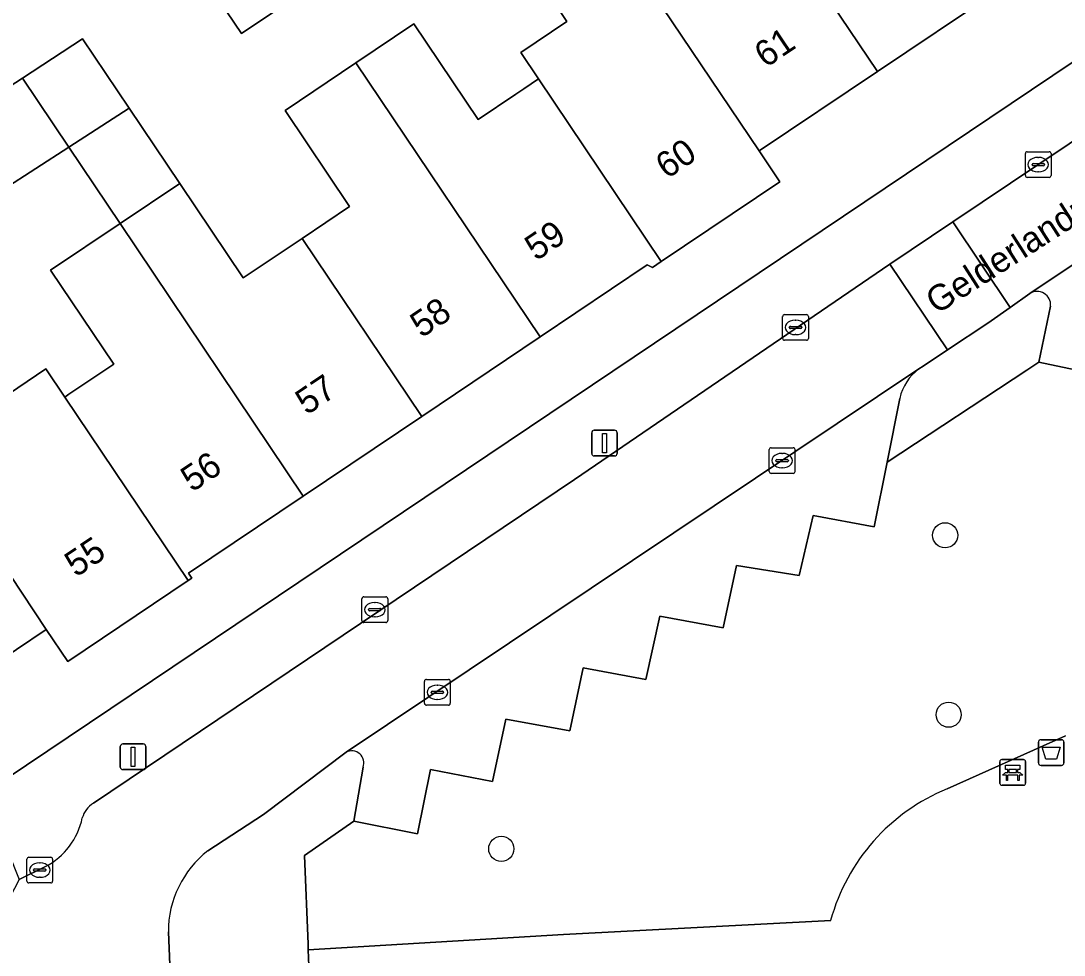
# Model space of a CAD drawing. Extents: x 158352 to 159489, y 383828 to 384603.
# Drawn here: x 158904.38 to 158944.92, y 384131.29 to 384167.59 of the extents above; entities that cross this region are included whole.
import ezdxf

# ---------------------------------------------------------------- set-up
doc = ezdxf.new("R2010")
doc.units = 0
for name, color, linetype in [('IMGEO_Afvalbak', 7, 'Continuous'), ('IMGEO_Bank', 7, 'Continuous'), ('IMGEO_Boom', 7, 'Continuous'), ('IMGEO_Erf', 7, 'Continuous'), ('IMGEO_Groenvoorziening', 7, 'Continuous'), ('IMGEO_Kolk', 7, 'Continuous'), ('IMGEO_Lichtmast', 7, 'Continuous'), ('IMGEO_Openbare_ruimte_label', 7, 'Continuous'), ('IMGEO_Pand', 7, 'Continuous'), ('IMGEO_Pand_nummerreeks', 7, 'Continuous'), ('IMGEO_Parkeervlak_open', 7, 'Continuous'), ('IMGEO_Rijbaan_lokaal_open', 7, 'Continuous'), ('IMGEO_Voetpad_halfverhard', 7, 'Continuous'), ('IMGEO_Voetpad_open', 7, 'Continuous')]:
    doc.layers.add(name, color=color, linetype=linetype)

msp = doc.modelspace()

# ---------------------------------------------------------------- linework, layer by layer
at = {"layer": 'IMGEO_Afvalbak'}
for p, q in [((158943.919, 384138.759), (158943.919, 384139.559)), ((158943.919, 384139.559), (158943.919, 384138.759)), ((158944.019, 384139.659), (158944.809, 384139.659)), ((158944.809, 384139.659), (158944.019, 384139.659)), ((158944.909, 384139.559), (158944.909, 384138.759)), ((158944.909, 384138.759), (158944.909, 384139.559)), ((158944.809, 384138.659), (158944.019, 384138.659)), ((158944.019, 384138.659), (158944.809, 384138.659))]:
    msp.add_line(p, q, dxfattribs=at)
msp.add_lwpolyline([(158944.062, 384139.373), (158944.766, 384139.373), (158944.617, 384138.903), (158944.211, 384138.903), (158944.062, 384139.373)], dxfattribs=at)
for centre, start, end in [((158944.019, 384139.559), 90, 180), ((158944.019, 384139.559), 90, 180), ((158944.809, 384139.559), 0, 90), ((158944.809, 384139.559), 360, 90), ((158944.019, 384138.759), 180, 270), ((158944.019, 384138.759), 180, 270), ((158944.809, 384138.759), 270, 0), ((158944.809, 384138.759), 270, 0)]:
    msp.add_arc(centre, 0.1, start, end, dxfattribs=at)
at = {"layer": 'IMGEO_Bank'}
for p, q in [((158942.419, 384137.961), (158942.419, 384138.802)), ((158942.419, 384138.802), (158942.419, 384137.961)), ((158942.494, 384138.886), (158943.335, 384138.886)), ((158943.335, 384138.886), (158942.494, 384138.886)), ((158943.419, 384138.811), (158943.419, 384137.97)), ((158943.419, 384137.97), (158943.419, 384138.811)), ((158942.728, 384138.392), (158942.728, 384138.498)), ((158942.772, 384138.498), (158942.772, 384138.392)), ((158943.06, 384138.504), (158942.778, 384138.504)), ((158942.778, 384138.386), (158943.06, 384138.386)), ((158943.066, 384138.392), (158943.066, 384138.498)), ((158943.11, 384138.498), (158943.11, 384138.392)), ((158943.116, 384138.284), (158942.723, 384138.284)), ((158943.344, 384137.886), (158942.503, 384137.886)), ((158942.503, 384137.886), (158943.344, 384137.886))]:
    msp.add_line(p, q, dxfattribs=at)
for points in [[(158942.666, 384138.284), (158942.524, 384138.284), (158942.636, 384138.386), (158942.722, 384138.386)], [(158942.722, 384138.504), (158942.636, 384138.504), (158942.636, 384138.665), (158943.199, 384138.665), (158943.199, 384138.504), (158943.116, 384138.504)], [(158943.116, 384138.386), (158943.199, 384138.386), (158943.311, 384138.284), (158943.172, 384138.284)], [(158942.716, 384138.277), (158942.716, 384138.07), (158942.673, 384138.07), (158942.673, 384138.277)], [(158943.166, 384138.277), (158943.166, 384138.07), (158943.122, 384138.07), (158943.122, 384138.277)]]:
    msp.add_lwpolyline(points, dxfattribs=at)
for centre, radius, start, end in [((158942.497, 384138.808), 0.0779, 92.4484, 184.2845), ((158942.497, 384138.808), 0.0779, 92.4484, 184.2845), ((158943.341, 384138.808), 0.0779, 2.4484, 94.2845), ((158943.341, 384138.808), 0.0779, 2.4484, 94.2845), ((158942.721, 384138.497), 0.00671, 2.8957, 87.1043), ((158942.721, 384138.393), 0.00671, 272.8957, 357.1043), ((158942.778, 384138.497), 0.00671, 92.8957, 177.1043), ((158942.778, 384138.393), 0.00671, 182.8957, 267.1043), ((158943.06, 384138.497), 0.00671, 2.8957, 87.1043), ((158943.06, 384138.393), 0.00671, 272.8957, 357.1043), ((158943.117, 384138.497), 0.00671, 92.8957, 177.1043), ((158943.117, 384138.393), 0.00671, 182.8957, 267.1043), ((158942.497, 384137.964), 0.0779, 182.4484, 274.2845), ((158942.497, 384137.964), 0.0779, 182.4484, 274.2845), ((158942.666, 384138.277), 0.00671, 2.8957, 87.1043), ((158942.723, 384138.277), 0.00671, 92.8957, 177.1043), ((158943.115, 384138.277), 0.00671, 2.8957, 87.1043), ((158943.172, 384138.277), 0.00671, 92.8957, 177.1043), ((158943.341, 384137.964), 0.0779, 272.4484, 4.2845), ((158943.341, 384137.964), 0.0779, 272.4484, 4.2845)]:
    msp.add_arc(centre, radius, start, end, dxfattribs=at)
at = {"layer": 'IMGEO_Boom'}
for centre in [(158940.292, 384147.602), (158940.43, 384140.63), (158923.046, 384135.417)]:
    msp.add_circle(centre, 0.489, dxfattribs=at)
at = {"layer": 'IMGEO_Erf'}
for points in [[(158942.263, 384168.715), (158937.66, 384165.622), (158933.069, 384162.537), (158933.874, 384161.338), (158929.263, 384158.239), (158928.917, 384158.007), (158928.717, 384158.105), (158924.553, 384155.307), (158919.952, 384152.215), (158915.351, 384149.124), (158910.891, 384146.127), (158911.02, 384145.936), (158910.878, 384145.84), (158906.196, 384142.695), (158905.358, 384143.942), (158900.735, 384140.836), (158902.964, 384137.583), (158985.981, 384193.365)], [(158901.912, 384163.736), (158904.435, 384165.362), (158906.776, 384166.896), (158908.583, 384164.205), (158910.552, 384161.273), (158913.019, 384157.601), (158915.301, 384159.135), (158917.151, 384160.378), (158914.641, 384164.113), (158917.393, 384165.962), (158919.642, 384167.473), (158922.143, 384163.753), (158923.61, 384164.739), (158923.924, 384164.95), (158924.495, 384165.334), (158923.801, 384166.367), (158925.595, 384167.573), (158923.12, 384171.257)], [(158903.155, 384152.593), (158905.348, 384154.067), (158906.084, 384152.973), (158906.243, 384153.08), (158906.627, 384153.338), (158907.984, 384154.25), (158905.531, 384157.899), (158908.232, 384159.714), (158906.237, 384162.682), (158903.677, 384161.02)]]:
    msp.add_lwpolyline(points, dxfattribs=at)
msp.add_lwpolyline([(158917.782, 384170.349), (158915.482, 384168.806), (158912.944, 384167.102), (158911.211, 384169.682), (158913.748, 384171.385), (158916.049, 384172.929)], close=True, dxfattribs=at)
at = {"layer": 'IMGEO_Groenvoorziening'}
for points in [[(158946.333, 384153.827), (158943.936, 384154.326), (158943.468, 384154.018), (158938.034, 384150.441), (158937.532, 384147.926), (158935.169, 384148.368), (158934.626, 384146.044), (158932.187, 384146.428), (158931.672, 384143.999), (158929.211, 384144.465), (158928.666, 384141.993), (158926.231, 384142.453), (158925.71, 384140.006), (158923.222, 384140.46), (158922.709, 384138.037), (158920.299, 384138.504), (158919.784, 384136.005), (158917.309, 384136.495), (158915.398, 384135.155), (158915.534, 384131.716), (158915.543, 384131.49), (158925.46, 384132.091), (158935.845, 384132.635)], [(158940.37, 384137.749), (158944.974, 384139.808)]]:
    msp.add_lwpolyline(points, dxfattribs=at)
msp.add_arc((158943.309, 384130.589), 7.74, 112.32, 164.6735, dxfattribs=at)
at = {"layer": 'IMGEO_Kolk'}
for p, q in [((158943.411, 384161.58), (158943.411, 384162.432)), ((158943.486, 384162.506), (158944.338, 384162.506)), ((158943.899, 384162.286), (158943.924, 384162.286)), ((158944.412, 384162.432), (158944.412, 384161.58)), ((158943.67, 384162), (158943.67, 384162.012)), ((158944.108, 384161.963), (158943.71, 384161.963)), ((158943.713, 384162.049), (158944.111, 384162.049)), ((158944.154, 384162.012), (158944.154, 384162)), ((158944.338, 384161.506), (158943.486, 384161.506)), ((158943.922, 384161.726), (158943.897, 384161.726)), ((158934.054, 384156.178), (158934.906, 384156.178)), ((158933.979, 384155.252), (158933.979, 384156.104)), ((158934.467, 384155.958), (158934.492, 384155.958)), ((158934.98, 384156.104), (158934.98, 384155.252)), ((158934.238, 384155.672), (158934.238, 384155.684)), ((158934.676, 384155.635), (158934.278, 384155.635)), ((158934.281, 384155.721), (158934.679, 384155.721)), ((158934.49, 384155.398), (158934.465, 384155.398)), ((158934.722, 384155.684), (158934.722, 384155.672)), ((158934.906, 384155.178), (158934.054, 384155.178)), ((158933.457, 384150.078), (158933.457, 384150.93)), ((158933.532, 384151.004), (158934.384, 384151.004)), ((158934.458, 384150.93), (158934.458, 384150.078)), ((158933.716, 384150.498), (158933.716, 384150.51)), ((158933.759, 384150.547), (158934.157, 384150.547)), ((158933.945, 384150.784), (158933.97, 384150.784)), ((158934.2, 384150.51), (158934.2, 384150.498)), ((158934.154, 384150.461), (158933.756, 384150.461)), ((158933.968, 384150.224), (158933.943, 384150.224)), ((158934.384, 384150.004), (158933.532, 384150.004)), ((158917.705, 384145.21), (158918.557, 384145.21)), ((158917.63, 384144.284), (158917.63, 384145.136)), ((158918.118, 384144.99), (158918.143, 384144.99)), ((158918.631, 384145.136), (158918.631, 384144.284)), ((158917.889, 384144.704), (158917.889, 384144.716)), ((158918.327, 384144.667), (158917.929, 384144.667)), ((158917.932, 384144.753), (158918.33, 384144.753)), ((158918.141, 384144.43), (158918.116, 384144.43)), ((158918.373, 384144.716), (158918.373, 384144.704)), ((158918.557, 384144.21), (158917.705, 384144.21)), ((158920.135, 384142), (158920.987, 384142)), ((158920.06, 384141.074), (158920.06, 384141.926)), ((158920.548, 384141.78), (158920.573, 384141.78)), ((158921.061, 384141.926), (158921.061, 384141.074)), ((158920.319, 384141.494), (158920.319, 384141.506)), ((158920.757, 384141.457), (158920.359, 384141.457)), ((158920.362, 384141.543), (158920.76, 384141.543)), ((158920.571, 384141.22), (158920.546, 384141.22)), ((158920.803, 384141.506), (158920.803, 384141.494)), ((158920.987, 384141), (158920.135, 384141)), ((158904.684, 384135.091), (158905.536, 384135.091)), ((158904.609, 384134.165), (158904.609, 384135.017)), ((158905.097, 384134.871), (158905.122, 384134.871)), ((158905.61, 384135.017), (158905.61, 384134.165)), ((158904.868, 384134.585), (158904.868, 384134.597)), ((158905.306, 384134.548), (158904.908, 384134.548)), ((158904.911, 384134.634), (158905.309, 384134.634)), ((158905.12, 384134.311), (158905.095, 384134.311)), ((158905.352, 384134.597), (158905.352, 384134.585)), ((158905.536, 384134.091), (158904.684, 384134.091))]:
    msp.add_line(p, q, dxfattribs=at)
for points in [[(158943.411, 384161.58), (158943.411, 384162.432)], [(158943.486, 384162.506), (158944.338, 384162.506)], [(158944.412, 384162.432), (158944.412, 384161.58)], [(158944.338, 384161.506), (158943.486, 384161.506)], [(158934.054, 384156.178), (158934.906, 384156.178)], [(158933.979, 384155.252), (158933.979, 384156.104)], [(158934.98, 384156.104), (158934.98, 384155.252)], [(158934.906, 384155.178), (158934.054, 384155.178)], [(158933.457, 384150.078), (158933.457, 384150.93)], [(158933.532, 384151.004), (158934.384, 384151.004)], [(158934.458, 384150.93), (158934.458, 384150.078)], [(158934.384, 384150.004), (158933.532, 384150.004)], [(158917.705, 384145.21), (158918.557, 384145.21)], [(158917.63, 384144.284), (158917.63, 384145.136)], [(158918.631, 384145.136), (158918.631, 384144.284)], [(158918.557, 384144.21), (158917.705, 384144.21)], [(158920.135, 384142), (158920.987, 384142)], [(158920.06, 384141.074), (158920.06, 384141.926)], [(158921.061, 384141.926), (158921.061, 384141.074)], [(158920.987, 384141), (158920.135, 384141)], [(158904.684, 384135.091), (158905.536, 384135.091)], [(158904.609, 384134.165), (158904.609, 384135.017)], [(158905.61, 384135.017), (158905.61, 384134.165)], [(158905.536, 384134.091), (158904.684, 384134.091)]]:
    msp.add_lwpolyline(points, dxfattribs=at)
for centre, radius, start, end in [((158943.488, 384162.43), 0.0765, 91.552, 178.448), ((158943.488, 384162.43), 0.0765, 91.552, 178.448), ((158944.336, 384162.43), 0.0765, 1.552, 88.448), ((158944.336, 384162.43), 0.0765, 1.552, 88.448), ((158943.71, 384162.009), 0.0403, 85.8775, 175.7526), ((158943.707, 384161.999), 0.0366, 178.938, 274.7102), ((158944.111, 384162.006), 0.043, 264.8664, 352.4533), ((158944.115, 384162.011), 0.0386, 1.7309, 96.639), ((158943.488, 384161.582), 0.0765, 181.552, 268.448), ((158943.488, 384161.582), 0.0765, 181.552, 268.448), ((158944.336, 384161.582), 0.0765, 271.552, 358.448), ((158944.336, 384161.582), 0.0765, 271.552, 358.448), ((158934.056, 384156.102), 0.0765, 91.552, 178.448), ((158934.056, 384156.102), 0.0765, 91.552, 178.448), ((158934.904, 384156.102), 0.0765, 1.552, 88.448), ((158934.904, 384156.102), 0.0765, 1.552, 88.448), ((158934.278, 384155.681), 0.0403, 85.8775, 175.7526), ((158934.275, 384155.671), 0.0366, 178.938, 274.7102), ((158934.679, 384155.678), 0.043, 264.8664, 352.4533), ((158934.683, 384155.683), 0.0386, 1.7309, 96.639), ((158934.056, 384155.254), 0.0765, 181.552, 268.448), ((158934.056, 384155.254), 0.0765, 181.552, 268.448), ((158934.904, 384155.254), 0.0765, 271.552, 358.448), ((158934.904, 384155.254), 0.0765, 271.552, 358.448), ((158933.534, 384150.928), 0.0765, 91.552, 178.448), ((158933.534, 384150.928), 0.0765, 91.552, 178.448), ((158934.382, 384150.928), 0.0765, 1.552, 88.448), ((158934.382, 384150.928), 0.0765, 1.552, 88.448), ((158933.756, 384150.507), 0.0403, 85.8775, 175.7526), ((158933.753, 384150.497), 0.0366, 178.938, 274.7102), ((158934.157, 384150.504), 0.043, 264.8664, 352.4533), ((158934.161, 384150.509), 0.0386, 1.7309, 96.639), ((158933.534, 384150.08), 0.0765, 181.552, 268.448), ((158933.534, 384150.08), 0.0765, 181.552, 268.448), ((158934.382, 384150.08), 0.0765, 271.552, 358.448), ((158934.382, 384150.08), 0.0765, 271.552, 358.448), ((158917.707, 384145.134), 0.0765, 91.552, 178.448), ((158917.707, 384145.134), 0.0765, 91.552, 178.448), ((158918.555, 384145.134), 0.0765, 1.552, 88.448), ((158918.555, 384145.134), 0.0765, 1.552, 88.448), ((158917.929, 384144.713), 0.0403, 85.8775, 175.7526), ((158917.926, 384144.703), 0.0366, 178.938, 274.7102), ((158918.33, 384144.71), 0.043, 264.8664, 352.4533), ((158918.334, 384144.715), 0.0386, 1.7309, 96.639), ((158917.707, 384144.286), 0.0765, 181.552, 268.448), ((158917.707, 384144.286), 0.0765, 181.552, 268.448), ((158918.555, 384144.286), 0.0765, 271.552, 358.448), ((158918.555, 384144.286), 0.0765, 271.552, 358.448), ((158920.137, 384141.924), 0.0765, 91.552, 178.448), ((158920.137, 384141.924), 0.0765, 91.552, 178.448), ((158920.985, 384141.924), 0.0765, 1.552, 88.448), ((158920.985, 384141.924), 0.0765, 1.552, 88.448), ((158920.359, 384141.503), 0.0403, 85.8775, 175.7526), ((158920.356, 384141.493), 0.0366, 178.938, 274.7102), ((158920.76, 384141.5), 0.043, 264.8664, 352.4533), ((158920.764, 384141.505), 0.0386, 1.7309, 96.639), ((158920.137, 384141.076), 0.0765, 181.552, 268.448), ((158920.137, 384141.076), 0.0765, 181.552, 268.448), ((158920.985, 384141.076), 0.0765, 271.552, 358.448), ((158920.985, 384141.076), 0.0765, 271.552, 358.448), ((158904.686, 384135.015), 0.0765, 91.552, 178.448), ((158904.686, 384135.015), 0.0765, 91.552, 178.448), ((158905.534, 384135.015), 0.0765, 1.552, 88.448), ((158905.534, 384135.015), 0.0765, 1.552, 88.448), ((158904.908, 384134.594), 0.0403, 85.8775, 175.7526), ((158904.905, 384134.584), 0.0366, 178.938, 274.7102), ((158905.309, 384134.591), 0.043, 264.8664, 352.4533), ((158905.313, 384134.596), 0.0386, 1.7309, 96.639), ((158904.686, 384134.167), 0.0765, 181.552, 268.448), ((158904.686, 384134.167), 0.0765, 181.552, 268.448), ((158905.534, 384134.167), 0.0765, 271.552, 358.448), ((158905.534, 384134.167), 0.0765, 271.552, 358.448)]:
    msp.add_arc(centre, radius, start, end, dxfattribs=at)
for centre, major_axis, ratio, start_param, end_param in [((158943.898, 384162.006), (-0.387, 0.002), 0.722429, 4.712389, 7.853982), ((158943.923, 384162.006), (-0.39, 0.002), 0.717154, 1.570796, 4.712389), ((158934.466, 384155.678), (-0.387, 0.002), 0.722429, 4.712389, 7.853982), ((158934.491, 384155.678), (-0.39, 0.002), 0.717154, 1.570796, 4.712389), ((158933.944, 384150.504), (-0.387, 0.002), 0.722429, 4.712389, 7.853982), ((158933.969, 384150.504), (-0.39, 0.002), 0.717154, 1.570796, 4.712389), ((158918.117, 384144.71), (-0.387, 0.002), 0.722429, 4.712389, 7.853982), ((158918.142, 384144.71), (-0.39, 0.002), 0.717154, 1.570796, 4.712389), ((158920.547, 384141.5), (-0.387, 0.002), 0.722429, 4.712389, 7.853982), ((158920.572, 384141.5), (-0.39, 0.002), 0.717154, 1.570796, 4.712389), ((158905.096, 384134.591), (-0.387, 0.002), 0.722429, 4.712389, 7.853982), ((158905.121, 384134.591), (-0.39, 0.002), 0.717154, 1.570796, 4.712389)]:
    msp.add_ellipse(centre, major_axis=major_axis, ratio=ratio, start_param=start_param, end_param=end_param, dxfattribs=at)
at = {"layer": 'IMGEO_Lichtmast'}
for p, q in [((158926.557, 384150.784), (158926.557, 384151.584)), ((158926.557, 384151.584), (158926.557, 384150.784)), ((158926.657, 384151.684), (158927.447, 384151.684)), ((158927.447, 384151.684), (158926.657, 384151.684)), ((158927.547, 384151.584), (158927.547, 384150.784)), ((158927.547, 384150.784), (158927.547, 384151.584)), ((158927.447, 384150.684), (158926.657, 384150.684)), ((158926.657, 384150.684), (158927.447, 384150.684)), ((158908.239, 384138.594), (158908.239, 384139.394)), ((158908.239, 384139.394), (158908.239, 384138.594)), ((158908.339, 384139.494), (158909.129, 384139.494)), ((158909.129, 384139.494), (158908.339, 384139.494)), ((158909.229, 384139.394), (158909.229, 384138.594)), ((158909.229, 384138.594), (158909.229, 384139.394)), ((158909.129, 384138.494), (158908.339, 384138.494)), ((158908.339, 384138.494), (158909.129, 384138.494))]:
    msp.add_line(p, q, dxfattribs=at)
for points in [[(158926.977, 384151.559), (158927.127, 384151.559), (158927.127, 384150.809), (158926.977, 384150.809), (158926.977, 384151.559)], [(158908.659, 384139.369), (158908.809, 384139.369), (158908.809, 384138.619), (158908.659, 384138.619), (158908.659, 384139.369)]]:
    msp.add_lwpolyline(points, dxfattribs=at)
for centre, start, end in [((158926.657, 384151.584), 90, 180), ((158926.657, 384151.584), 90, 180), ((158927.447, 384151.584), 0, 90), ((158927.447, 384151.584), 360, 90), ((158926.657, 384150.784), 180, 270), ((158926.657, 384150.784), 180, 270), ((158927.447, 384150.784), 270, 0), ((158927.447, 384150.784), 270, 0), ((158908.339, 384139.394), 90, 180), ((158908.339, 384139.394), 90, 180), ((158909.129, 384139.394), 0, 90), ((158909.129, 384139.394), 360, 90), ((158908.339, 384138.594), 180, 270), ((158908.339, 384138.594), 180, 270), ((158909.129, 384138.594), 270, 0), ((158909.129, 384138.594), 270, 0)]:
    msp.add_arc(centre, 0.1, start, end, dxfattribs=at)
at = {"layer": 'IMGEO_Pand'}
for points in [[(158935.141, 384179.308), (158932.202, 384177.334), (158934.63, 384173.72), (158932.968, 384172.604), (158937.66, 384165.622), (158942.263, 384168.715)], [(158925.926, 384173.142), (158933.069, 384162.537), (158937.66, 384165.622), (158932.968, 384172.604), (158930.522, 384170.96), (158928.082, 384174.591)], [(158925.926, 384173.142), (158923.12, 384171.257), (158925.595, 384167.573), (158923.801, 384166.367), (158924.495, 384165.334), (158929.263, 384158.239), (158933.874, 384161.338), (158933.069, 384162.537)], [(158913.748, 384171.385), (158911.211, 384169.682), (158912.944, 384167.102), (158915.482, 384168.806)], [(158924.495, 384165.334), (158923.924, 384164.95), (158923.61, 384164.739), (158922.143, 384163.753), (158919.642, 384167.473), (158917.393, 384165.962), (158924.553, 384155.307), (158928.717, 384158.105), (158928.917, 384158.007), (158929.263, 384158.239)], [(158906.776, 384166.896), (158904.435, 384165.362), (158906.237, 384162.682), (158908.583, 384164.205)], [(158924.553, 384155.307), (158917.393, 384165.962), (158914.641, 384164.113), (158917.151, 384160.378), (158915.301, 384159.135), (158919.952, 384152.215)], [(158904.435, 384165.362), (158901.912, 384163.736), (158903.677, 384161.02), (158906.237, 384162.682)], [(158908.583, 384164.205), (158906.237, 384162.682), (158908.232, 384159.714), (158910.552, 384161.273)], [(158908.232, 384159.714), (158915.351, 384149.124), (158919.952, 384152.215), (158915.301, 384159.135), (158913.019, 384157.601), (158910.552, 384161.273)], [(158908.232, 384159.714), (158905.531, 384157.899), (158907.984, 384154.25), (158906.627, 384153.338), (158906.243, 384153.08), (158906.084, 384152.973), (158910.878, 384145.84), (158911.02, 384145.936), (158910.891, 384146.127), (158915.351, 384149.124)], [(158906.084, 384152.973), (158905.348, 384154.067), (158903.155, 384152.593), (158900.779, 384156.13), (158900.179, 384155.727), (158898.369, 384154.511), (158905.358, 384143.942), (158906.196, 384142.695), (158910.878, 384145.84)], [(158905.358, 384143.942), (158898.369, 384154.511), (158896.028, 384152.938), (158898.481, 384149.285), (158896.123, 384147.701), (158900.735, 384140.836)]]:
    msp.add_lwpolyline(points, close=True, dxfattribs=at)
at = {"layer": 'IMGEO_Parkeervlak_open'}
for points in [[(158965.432, 384171.613), (158943.586, 384157)], [(158944.39, 384156.508), (158943.936, 384154.326), (158946.333, 384153.827), (158946.816, 384156.22), (158949.22, 384155.771), (158949.725, 384158.18), (158952.106, 384157.731), (158952.582, 384160.203), (158955.01, 384159.702), (158955.523, 384162.086), (158957.941, 384161.655), (158958.467, 384164.069), (158960.887, 384163.61), (158961.363, 384165.968), (158963.745, 384165.513), (158964.22, 384167.84), (158964.759, 384170.476)], [(158939.275, 384154.07), (158917.016, 384139.173)], [(158917.673, 384138.59), (158917.309, 384136.495), (158919.784, 384136.005), (158920.299, 384138.504), (158922.709, 384138.037), (158923.222, 384140.46), (158925.71, 384140.006), (158926.231, 384142.453), (158928.666, 384141.993), (158929.211, 384144.465), (158931.672, 384143.999), (158932.187, 384146.428), (158934.626, 384146.044), (158935.169, 384148.368), (158937.532, 384147.926), (158938.034, 384150.441), (158938.529, 384152.923)]]:
    msp.add_lwpolyline(points, dxfattribs=at)
for centre, radius, start, end in [((158943.863, 384156.549), 0.529, 355.5648, 121.5069), ((158940.443, 384152.494), 1.962, 126.5518, 167.3689), ((158917.233, 384138.755), 0.47, 339.4327, 117.3977)]:
    msp.add_arc(centre, radius, start, end, dxfattribs=at)
at = {"layer": 'IMGEO_Rijbaan_lokaal_open'}
for points in [[(158940.594, 384159.779), (158942.823, 384156.459), (158943.586, 384157), (158965.432, 384171.613), (158966.537, 384172.358), (158964.303, 384175.685)], [(158940.594, 384159.779), (158938.144, 384158.136), (158940.381, 384154.803), (158941.955, 384155.844), (158942.823, 384156.459)]]:
    msp.add_lwpolyline(points, close=True, dxfattribs=at)
for points in [[(158911.643, 384135.339), (158913.8, 384136.746), (158917.016, 384139.173), (158939.275, 384154.07), (158939.434, 384154.177), (158940.381, 384154.803), (158938.144, 384158.136), (158925.886, 384149.768), (158907.192, 384137.187)], [(158905.336, 384134.731), (158904.315, 384134.226), (158901.467, 384128.786)], [(158910.286, 384128.033), (158910.106, 384132.189)]]:
    msp.add_lwpolyline(points, dxfattribs=at)
for centre, radius, start, end in [((158907.74, 384136.324), 1.023, 122.4318, 163.2826), ((158904.049, 384137.185), 2.771, 297.6835, 348.1987), ((158914.087, 384132.197), 3.981, 127.8698, 180.1113)]:
    msp.add_arc(centre, radius, start, end, dxfattribs=at)
at = {"layer": 'IMGEO_Voetpad_halfverhard'}
for points in [[(158944.974, 384139.808), (158940.37, 384137.749)], [(158935.845, 384132.635), (158925.46, 384132.091), (158915.543, 384131.49), (158915.637, 384129.002), (158915.645, 384128.805), (158936.38, 384129.934)]]:
    msp.add_lwpolyline(points, dxfattribs=at)
msp.add_arc((158943.309, 384130.589), 7.74, 112.32, 164.6735, dxfattribs=at)
at = {"layer": 'IMGEO_Voetpad_open'}
for points in [[(158925.886, 384149.768), (158938.144, 384158.136), (158940.594, 384159.779), (158964.303, 384175.685), (158966.736, 384177.317), (158986.851, 384190.812), (158985.981, 384193.365), (158902.964, 384137.583), (158904.315, 384134.226), (158905.336, 384134.731)], [(158943.586, 384157), (158942.823, 384156.459), (158941.955, 384155.844), (158940.381, 384154.803), (158939.434, 384154.177), (158939.275, 384154.07)], [(158938.529, 384152.923), (158938.034, 384150.441), (158943.468, 384154.018), (158943.936, 384154.326), (158944.39, 384156.508)], [(158907.192, 384137.187), (158925.886, 384149.768)], [(158917.016, 384139.173), (158913.8, 384136.746), (158911.643, 384135.339)], [(158915.722, 384123.984), (158918.255, 384124.726), (158915.761, 384126.104), (158915.645, 384128.805), (158915.637, 384129.002), (158915.543, 384131.49), (158915.534, 384131.716), (158915.398, 384135.155), (158917.309, 384136.495), (158917.673, 384138.59)], [(158910.106, 384132.189), (158910.286, 384128.033)]]:
    msp.add_lwpolyline(points, dxfattribs=at)
for centre, radius, start, end in [((158943.863, 384156.549), 0.529, 355.5648, 121.5069), ((158940.443, 384152.494), 1.962, 126.5518, 167.3689), ((158917.233, 384138.755), 0.47, 339.4327, 117.3977), ((158907.74, 384136.324), 1.023, 122.4318, 163.2826), ((158904.049, 384137.185), 2.771, 297.6835, 348.1987), ((158914.087, 384132.197), 3.981, 127.8698, 180.1113)]:
    msp.add_arc(centre, radius, start, end, dxfattribs=at)

# ---------------------------------------------------------------- texts
at = {"layer": 'IMGEO_Openbare_ruimte_label'}
msp.add_text('Gelderlandplein', height=1, rotation=32.6733, dxfattribs=at).set_placement((158939.96, 384156.165))
at = {"layer": 'IMGEO_Pand_nummerreeks'}
for s, rotation, p in [('61', 33.8992, (158933.319, 384165.741)), ('60', 33.9019, (158929.48, 384161.422)), ('59', 33.8962, (158924.397, 384158.239)), ('58', 33.8987, (158919.944, 384155.246)), ('57', 33.8987, (158915.484, 384152.25)), ('56', 33.8962, (158911.028, 384149.255)), ('55', 33.8962, (158906.517, 384145.947))]:
    msp.add_text(s, height=1, rotation=rotation, dxfattribs=at).set_placement(p)

doc.saveas('drawing.dxf')
